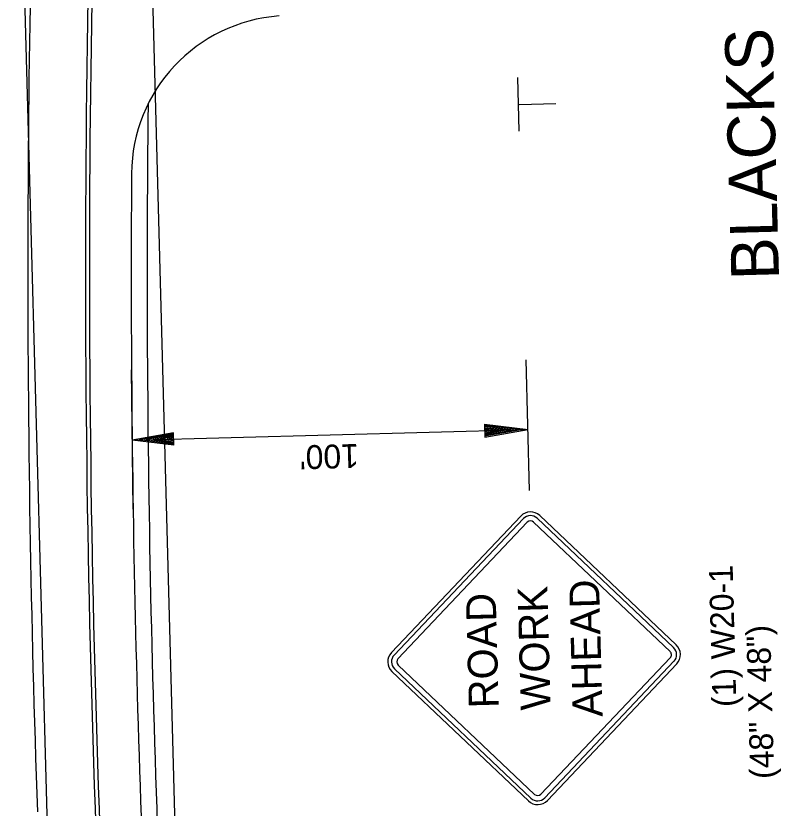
# Model space of a CAD drawing. Extents: x 1929653 to 1931621, y 596452 to 600944.
# Drawn here: x 1929835.6 to 1930124.2, y 598325 to 598623.7 of the extents above; entities that cross this region are included whole.
import ezdxf

# ---------------------------------------------------------------- set-up
doc = ezdxf.new("R2010")
doc.units = 0
for name, color, linetype in [('P_TC_Signs_Temporary', 7, 'Continuous'), ('R_Border', 7, 'Continuous'), ('R_Draft', 7, 'Continuous')]:
    doc.layers.add(name, color=color, linetype=linetype)

msp = doc.modelspace()

# ---------------------------------------------------------------- linework, layer by layer
at = {"layer": 'P_TC_Signs_Temporary'}
for p, q in [((1930026.01, 598435.13), (1929977.26, 598383.69)), ((1930027.03, 598434.17), (1929978.28, 598382.72)), ((1930028.46, 598432.81), (1929979.71, 598381.37)), ((1930082.29, 598384.12), (1930030.85, 598432.88)), ((1930083.65, 598385.55), (1930032.2, 598434.3)), ((1930084.61, 598386.57), (1930033.17, 598435.33)), ((1930033.6, 598330.29), (1930082.36, 598381.74)), ((1930035.03, 598328.94), (1930083.78, 598380.38)), ((1930036.05, 598327.97), (1930084.8, 598379.42)), ((1929977.45, 598376.53), (1930028.89, 598327.78)), ((1929978.42, 598377.55), (1930029.86, 598328.8)), ((1929979.77, 598378.98), (1930031.22, 598330.23))]:
    msp.add_line(p, q, dxfattribs=at)
for centre, radius, start, end in [((1930029.69, 598431.65), 5.06, 46.5377, 136.5377), ((1930029.69, 598431.65), 3.66, 46.5377, 136.5377), ((1930029.69, 598431.65), 1.69, 46.5377, 136.5377), ((1930081.13, 598382.9), 3.66, 316.5377, 46.5377), ((1930081.13, 598382.9), 5.06, 316.5377, 46.5377), ((1929980.93, 598380.21), 5.06, 136.5377, 226.5377), ((1929980.93, 598380.21), 3.66, 136.5377, 226.5377), ((1930081.13, 598382.9), 1.69, 316.5377, 46.5377), ((1929980.93, 598380.21), 1.69, 136.5377, 226.5377), ((1930032.38, 598331.45), 3.66, 226.5377, 316.5377), ((1930032.38, 598331.45), 1.69, 226.5377, 316.5377), ((1930032.38, 598331.45), 5.06, 226.5377, 316.5377)]:
    msp.add_arc(centre, radius, start, end, dxfattribs=at)
at = {"layer": 'R_Draft'}
for p, q in [((1929907.99, 597857.75), (1929883.87, 598756.49)), ((1929860.13, 597856.47), (1929835.62, 598755.2)), ((1930025.43, 598580.26), (1930024.89, 598600.45)), ((1930025.45, 598590.32), (1930039.23, 598590.69)), ((1930029.36, 598444.74), (1930028.03, 598494.06)), ((1929879.84, 598437.74), (1929879.25, 598490.25)), ((1930012.36, 598469.83), (1930028.74, 598467.82)), ((1930012.36, 598469.83), (1930012.49, 598464.93)), ((1930012.37, 598469.42), (1930026.01, 598467.74)), ((1930012.38, 598469), (1930023.21, 598467.67)), ((1929895.05, 598466.57), (1929879.49, 598463.81)), ((1929879.53, 598463.81), (1930028.74, 598467.82)), ((1929895.06, 598466.17), (1929882.1, 598463.88)), ((1929895.07, 598465.78), (1929884.78, 598463.95)), ((1929895.17, 598461.89), (1929895.05, 598466.57)), ((1930012.39, 598468.59), (1930020.49, 598467.59)), ((1930012.41, 598468.17), (1930017.72, 598467.52)), ((1930012.41, 598467.76), (1930015, 598467.45)), ((1930012.43, 598467), (1930015, 598467.45)), ((1930012.44, 598466.58), (1930017.72, 598467.52)), ((1930012.45, 598466.17), (1930020.49, 598467.59)), ((1930012.46, 598465.76), (1930023.21, 598467.67)), ((1930012.48, 598465.34), (1930026.01, 598467.74)), ((1930012.49, 598464.93), (1930028.74, 598467.82)), ((1929895.17, 598461.89), (1929879.49, 598463.81)), ((1929895.16, 598462.27), (1929882.1, 598463.88)), ((1929895.15, 598462.67), (1929884.78, 598463.95)), ((1929895.08, 598465.39), (1929887.39, 598464.02)), ((1929895.14, 598463.06), (1929887.39, 598464.02)), ((1929895.09, 598464.99), (1929890.03, 598464.09)), ((1929895.12, 598463.47), (1929890.03, 598464.09)), ((1929895.1, 598464.59), (1929892.64, 598464.16)), ((1929895.12, 598463.86), (1929892.64, 598464.16))]:
    msp.add_line(p, q, dxfattribs=at)
for centre, radius, start, end in [((1935592.2, 598528.17), 5752.08, 177.735604, 182.037539), ((1935591.45, 598528.15), 5729.58, 177.7558, 183.343096), ((1935591.45, 598528.15), 5728.08, 177.76852, 183.3431), ((1929939.23, 598563.83), 60, 94.1731, 179.6385), ((1935592.2, 598528.17), 5707.08, 179.37471, 183.3431), ((1935592.2, 598528.17), 5713.08, 179.63853, 183.3431)]:
    msp.add_arc(centre, radius, start, end, dxfattribs=at)

# ---------------------------------------------------------------- texts
at = {"layer": 'P_TC_Signs_Temporary'}
for s, p in [(' AHEAD ', (1930056.99, 598355.37)), ('WORK', (1930037.27, 598362.11)), (' ROAD ', (1930017.82, 598358.66))]:
    msp.add_text(s, height=11.25, rotation=91.5377, dxfattribs=at).set_placement(p)
at = {"layer": 'R_Border'}
for s, height, rotation, p in [('BLACKS FERRY RD.', 18, 91.5377, (1930123.42, 598524.34)), ("100'", 9, 181.5377, (1929964.85, 598462.35)), ('(1) W20-1', 9, 91.5377, (1930107.33, 598363.27)), ('(48" X 48")', 9, 91.5377, (1930121.56, 598336.14))]:
    msp.add_text(s, height=height, rotation=rotation, dxfattribs=at).set_placement(p)

doc.saveas('drawing.dxf')
